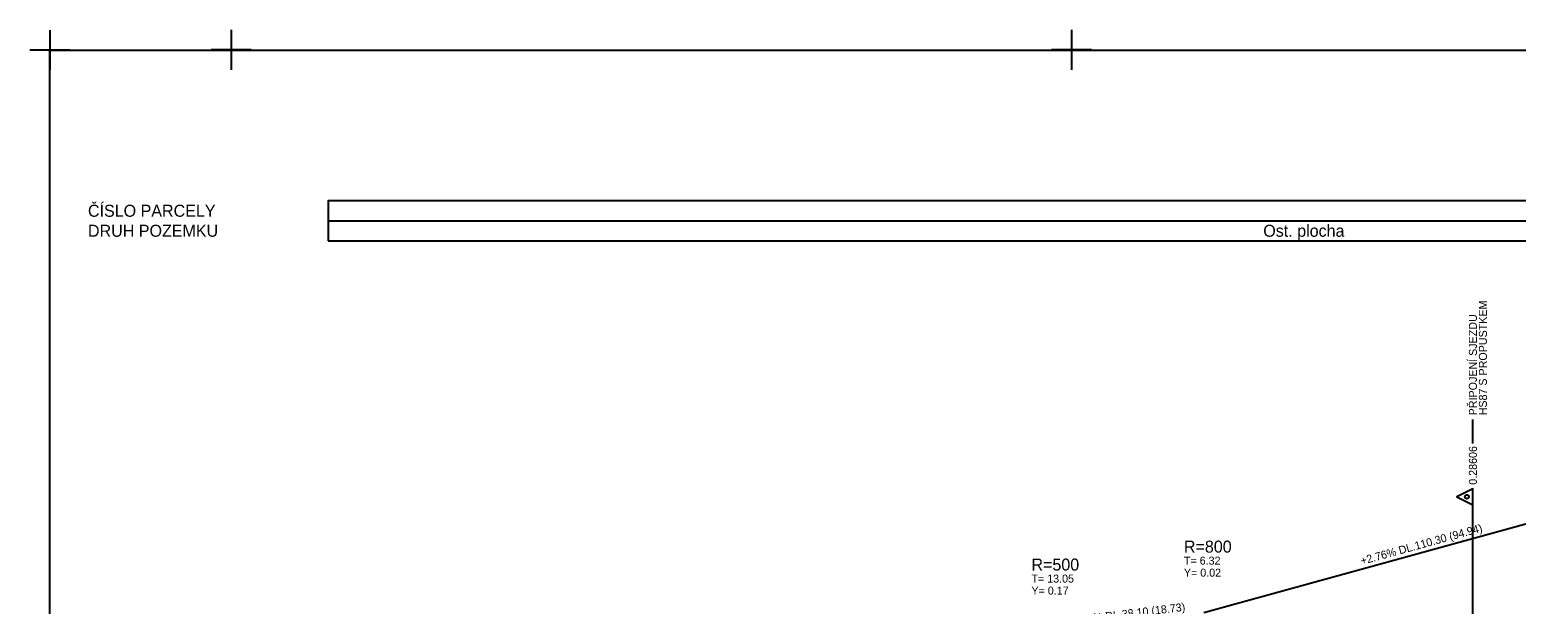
# Model space of a CAD drawing. Extents: x -5 to 681, y -26 to 404.
# Drawn here: x -4.5 to 366.9, y 260.8 to 404.4 of the extents above; entities that cross this region are included whole.
import ezdxf

# ---------------------------------------------------------------- set-up
doc = ezdxf.new("R2010")
doc.units = 0
for name, color, linetype in [('NOVY_STAV', 7, 'Continuous'), ('NS_OBLOUK', 7, 'Continuous'), ('POPISY_NAD_TERENEM', 7, 'Continuous'), ('TABULKY', 7, 'Continuous'), ('ZNACKY', 7, 'Continuous')]:
    doc.layers.add(name, color=color, linetype=linetype)

msp = doc.modelspace()

# ---------------------------------------------------------------- linework, layer by layer
for p, q in [((0.45, 404.23), (0.45, 394.23)), ((0.45, 404.23), (0.45, 394.23)), ((0.45, 404.23), (0.45, 394.23)), ((0.45, 404.23), (0.45, 394.23)), ((0.45, 404.23), (0.45, 394.23)), ((0.45, 404.23), (0.45, 394.23)), ((0.45, 404.23), (0.45, 394.23)), ((0.45, 404.23), (0.45, 394.23)), ((0.45, 404.23), (0.45, 394.23)), ((0.45, 404.23), (0.45, 394.23)), ((45.78, 404.35), (45.78, 394.35)), ((45.78, 404.35), (45.78, 394.35)), ((45.78, 404.35), (45.78, 394.35)), ((45.78, 404.35), (45.78, 394.35)), ((45.78, 404.35), (45.78, 394.35)), ((45.78, 404.35), (45.78, 394.35)), ((45.78, 404.35), (45.78, 394.35)), ((45.78, 404.35), (45.78, 394.35)), ((45.78, 404.35), (45.78, 394.35)), ((45.78, 404.35), (45.78, 394.35)), ((255.78, 404.31), (255.78, 394.31)), ((255.78, 404.31), (255.78, 394.31)), ((255.78, 404.31), (255.78, 394.31)), ((255.78, 404.31), (255.78, 394.31)), ((255.78, 404.31), (255.78, 394.31)), ((255.78, 404.31), (255.78, 394.31)), ((255.78, 404.31), (255.78, 394.31)), ((255.78, 404.31), (255.78, 394.31)), ((255.78, 404.31), (255.78, 394.31)), ((255.78, 404.31), (255.78, 394.31)), ((255.78, 404.31), (255.78, 394.31)), ((255.78, 404.31), (255.78, 394.31)), ((255.78, 404.31), (255.78, 394.31)), ((255.78, 404.31), (255.78, 394.31)), ((255.78, 404.31), (255.78, 394.31)), ((255.78, 404.31), (255.78, 394.31)), ((255.78, 404.31), (255.78, 394.31)), ((255.78, 404.31), (255.78, 394.31)), ((255.78, 404.31), (255.78, 394.31)), ((255.78, 404.31), (255.78, 394.31)), ((5.45, 399.23), (-4.55, 399.23)), ((5.45, 399.23), (-4.55, 399.23)), ((5.45, 399.23), (-4.55, 399.23)), ((5.45, 399.23), (-4.55, 399.23)), ((5.45, 399.23), (-4.55, 399.23)), ((5.45, 399.23), (-4.55, 399.23)), ((5.45, 399.23), (-4.55, 399.23)), ((5.45, 399.23), (-4.55, 399.23)), ((5.45, 399.23), (-4.55, 399.23)), ((5.45, 399.23), (-4.55, 399.23)), ((50.78, 399.35), (40.78, 399.35)), ((50.78, 399.35), (40.78, 399.35)), ((50.78, 399.35), (40.78, 399.35)), ((50.78, 399.35), (40.78, 399.35)), ((50.78, 399.35), (40.78, 399.35)), ((50.78, 399.35), (40.78, 399.35)), ((50.78, 399.35), (40.78, 399.35)), ((50.78, 399.35), (40.78, 399.35)), ((50.78, 399.35), (40.78, 399.35)), ((50.78, 399.35), (40.78, 399.35)), ((260.78, 399.31), (250.78, 399.31)), ((260.78, 399.31), (250.78, 399.31)), ((260.78, 399.31), (250.78, 399.31)), ((260.78, 399.31), (250.78, 399.31)), ((260.78, 399.31), (250.78, 399.31)), ((260.78, 399.31), (250.78, 399.31)), ((260.78, 399.31), (250.78, 399.31)), ((260.78, 399.31), (250.78, 399.31)), ((260.78, 399.31), (250.78, 399.31)), ((260.78, 399.31), (250.78, 399.31)), ((260.78, 399.31), (250.78, 399.31)), ((260.78, 399.31), (250.78, 399.31)), ((260.78, 399.31), (250.78, 399.31)), ((260.78, 399.31), (250.78, 399.31)), ((260.78, 399.31), (250.78, 399.31)), ((260.78, 399.31), (250.78, 399.31)), ((260.78, 399.31), (250.78, 399.31)), ((260.78, 399.31), (250.78, 399.31)), ((260.78, 399.31), (250.78, 399.31)), ((260.78, 399.31), (250.78, 399.31))]:
    msp.add_line(p, q)
msp.add_lwpolyline([(675.78, -20.77), (0.45, -20.77), (0.45, 399.23), (675.78, 399.23)], close=True)
at = {"layer": 'NOVY_STAV'}
msp.add_lwpolyline([(288.85, 258.7), (399.15, 289.13)], dxfattribs=at)
at = {"layer": 'POPISY_NAD_TERENEM'}
msp.add_lwpolyline([(356.06, 301), (356.06, 307)], dxfattribs=at)
at = {"layer": 'TABULKY'}
for points in [[(70, 351.62), (501.87, 351.62), (501.87, 361.62), (70, 361.62), (70, 351.62)], [(70, 356.62), (501.87, 356.62)]]:
    msp.add_lwpolyline(points, dxfattribs=at)
at = {"layer": 'ZNACKY'}
msp.add_lwpolyline([(356.06, 257.24), (356.06, 289.66), (352.06, 287.66), (356.06, 285.66)], dxfattribs=at)
msp.add_circle((354.56, 287.66), 0.5, dxfattribs=at)

# ---------------------------------------------------------------- texts
at = {"layer": 'NOVY_STAV'}
for s, rotation, p in [('+2.76% DL.110.30 (94.94)', 15.4248, (328.28, 270.62)), ('+1.18% DL.38.10 (18.73)', 6.7206, (254.51, 255.66))]:
    msp.add_text(s, height=2, rotation=rotation, dxfattribs=at).set_placement(p)
at = {"layer": 'NS_OBLOUK'}
for s, height, p in [('R=800', 3, (283.85, 273.7)), ('R=500', 3, (245.75, 269.21)), ('T= 6.32', 2, (283.85, 270.7)), ('T= 13.05', 2, (245.75, 266.21)), ('Y= 0.02', 2, (283.85, 267.7)), ('Y= 0.17', 2, (245.75, 263.21))]:
    msp.add_text(s, height=height, dxfattribs=at).set_placement(p)
at = {"layer": 'POPISY_NAD_TERENEM'}
for s, p in [('HS87 S PROPUSTKEM', (359.56, 308)), ('PŘIPOJENÍ SJEZDU', (357.06, 308))]:
    msp.add_text(s, height=2, rotation=90, dxfattribs=at).set_placement(p)
at = {"layer": 'TABULKY'}
for s, p in [('ČÍSLO PARCELY', (10, 357.62)), ('DRUH POZEMKU', (10, 352.62)), ('Ost. plocha', (303.68, 352.62))]:
    msp.add_text(s, height=3, dxfattribs=at).set_placement(p)
at = {"layer": 'ZNACKY'}
msp.add_text('0.28606', height=2, rotation=90, dxfattribs=at).set_placement((357.06, 290.66))

doc.saveas('drawing.dxf')
